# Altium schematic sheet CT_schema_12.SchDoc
size 226 x 144 mm
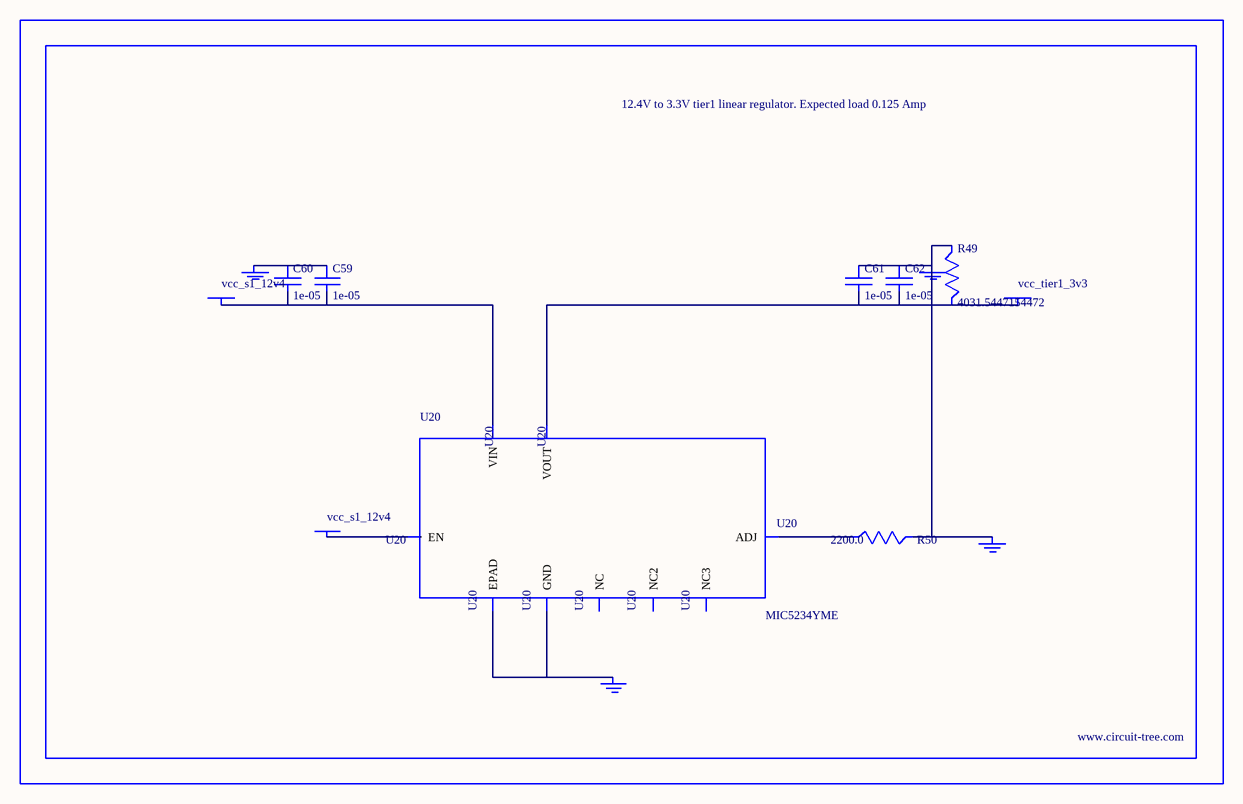
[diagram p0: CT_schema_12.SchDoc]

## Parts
BORDER11  (no value)
C59  1e-05  [C1210]
C60  1e-05  [C1210]
C61  1e-05  [C1210]
C62  1e-05  [C1210]
GND_INSTANCE_11_0  (no value)
GND_INSTANCE_11_1  (no value)
GND_INSTANCE_11_2  (no value)
GND_INSTANCE_11_3  (no value)
POWER_INSTANCE_11_0  vcc_tier1_3v3
POWER_INSTANCE_11_1  vcc_s1_12v4
POWER_INSTANCE_11_2  vcc_s1_12v4
R49  4031.5447154472  [R0603]
R50  2200.0  [R0603]
U20  MIC5234YME  [SOIC-8_EP]

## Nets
NetC59_1: C59.1 C60.1 GND_INSTANCE_11_3.0(GND)
NetC59_2: C59.2 C60.2 POWER_INSTANCE_11_2.0(PWR) U20.8(VIN)
NetC61_1: C61.1 C62.1 GND_INSTANCE_11_0.0(GND) GND_INSTANCE_11_1.0(GND) R49.1 R50.2
NetC61_2: C61.2 C62.2 POWER_INSTANCE_11_0.0(PWR) R49.2 U20.1(VOUT)
NetGND_INSTANCE_11_2_0: GND_INSTANCE_11_2.0(GND) U20.7(GND) U20.EPAD
NetPOWER_INSTANCE_11_1_0: POWER_INSTANCE_11_1.0(PWR) U20.5(EN)
NetR50_1: R50.1 U20.4(ADJ)

Not connected (* = marked no-connect by the designer): U20 2(NC) 3(NC2) 6(NC3)

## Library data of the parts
BORDER11 = BORDER_PAGE11
C59-C62 = C1210C106K5PACTU
GND_INSTANCE_11_0-GND_INSTANCE_11_3 = GND
POWER_INSTANCE_11_0-POWER_INSTANCE_11_2 = PWR
R49 = R49
R50 = RC0603JR-072K2L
